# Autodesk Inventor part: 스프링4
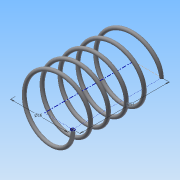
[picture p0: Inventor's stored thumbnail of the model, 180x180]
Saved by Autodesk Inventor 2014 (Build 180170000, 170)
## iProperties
Created: 2015-06
Part Number: 스프링4
Material: 강철, 연강
Document SubType Name: Modeling
Designer: Administrator
Density: 7.86 g/cm^3
Appearance: 강철
Mass: 1.5292 g
Surface Area: 7.8715 cm^2
Volume: 0.194555 cm^3
Author: Administrator
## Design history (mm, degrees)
sketch "스케치1"
  geometry: L1 (0, 0)-(8, 0); L2 (8, 0)-(8, 14.5); L3 (8, 14.5)-(0, 14.5); L4 (0, 14.5)-(0, 0); C1 r 0.5 at (8, 0)
  constraints: 8 end point, 2 parallel, 1 centre point, 1 coincident, 1 horizontal, 1 perpendicular
  dimensions: "d1" = 1 diameter of C1; "d2" = 16 diameter of L2 L4; "d3" = 14.5 distance of L1.end L2.end (derived)
feature "코일1" sketch "스케치1" pitch "d4" = 10; turns "d6" = 5; dims "d5" = 14.5 (= d3), "d7" = 0, angle "d8" = 90 deg, angle "d9" = 90 deg, "d10" = 0, "d11" = 0
sketch "스케치2"
  geometry: L1 (-8.5, 0)-(-7.5, 0) reference; 1 further point
  constraints: 1 horizontal alignment
extrude "돌출1" cut sketch "스케치2" stored distance "d12" = 10; taper "d13" = 0 deg
node "작업 평면1"
sketch "스케치3"
  geometry: L1 (8.5, 0)-(7.5, 0) reference; 1 further point
  constraints: 1 horizontal alignment
extrude "돌출2" cut sketch "스케치3" stored distance "d15" = 10; taper "d16" = 0 deg
node "솔리드1"
node "절단 모서리 투영1"
node "절단 모서리 투영2"
other parameters: "d14" = -14.5 (= -d3)
